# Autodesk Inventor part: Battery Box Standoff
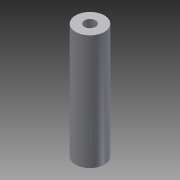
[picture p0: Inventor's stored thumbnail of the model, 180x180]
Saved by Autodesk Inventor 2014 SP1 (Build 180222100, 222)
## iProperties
Created: 2014-09
Part Number: Battery Box Standoff
Material: Aluminum 6061
Document SubType Name: Modeling
Designer: Michael
Density: 2.71 g/cm^3
Appearance: Aluminum - Flat
Author: Michael
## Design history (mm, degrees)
sketch "Sketch1"
  geometry: C1 r 6.35 at (0, 0); C2 r 2.489 at (0, 0); 1 further point
  constraints: 2 centre point, 2 coincident
  dimensions: "d0" = 12.7 diameter of C1; "d1" = 4.9784 diameter of C2
extrude "Extrusion1" new body sketch "Sketch1" distance "d2" = 50.8; taper "d3" = 0 deg
body "Solid1"
